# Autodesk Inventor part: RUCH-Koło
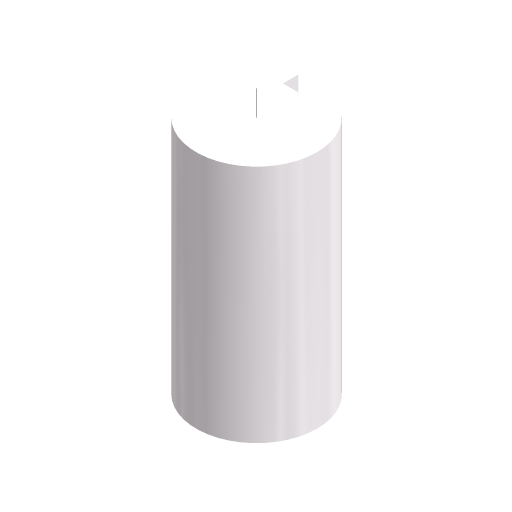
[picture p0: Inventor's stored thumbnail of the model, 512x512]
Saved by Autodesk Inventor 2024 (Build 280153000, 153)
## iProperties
Company: ATC
Created: 2023-03
Part Number: RUCH-Koło
Document SubType Name: Modeling
Designer: Andrzej Jaskulski
Manufacturer: Standard
Standards Organization: Custom
Material: Kurs-AJ
Density: 1 g/cm^3
Appearance: Kurs-AJ
Checked By: A.J.
Engr Approved By: Andrzej Jaskulski
Mfg Approved By: Andrzej Jaskulski
Authority: A.J.
DE: 30,000 mm
Title: A.J.: Kurs R2024-MEP
Author: Andrzej Jaskulski
Revision Number: 1/24
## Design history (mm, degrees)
sketch "Szkic1"
  geometry: C1 r 7.56 at (-49.399, 1.842)
  constraints: 1 centre point
extrude "Wyciągnięcie proste1" new body sketch "Szkic1" taper "d1" = 0 deg; distance "DE" = 30
sketch "Szkic2"
  geometry: L1 (-2.038, 11.253)-(1.49, 11.253); L2 (1.49, 11.253)-(1.49, 5.333); L3 (1.49, 5.333)-(-2.038, 5.333); L4 (-2.038, 5.333)-(-2.038, 11.253)
  constraints: 8 end point, 2 parallel, 1 horizontal, 1 perpendicular
extrude "Wyciągnięcie proste2" cut sketch "Szkic2" extent not by distance; stored distance "d2" = 30; taper "d3" = 0 deg
node "Oś"
node "Bryła1"
node "Korpusy bryłowe"
node "Korpusy powierzchniowe"
